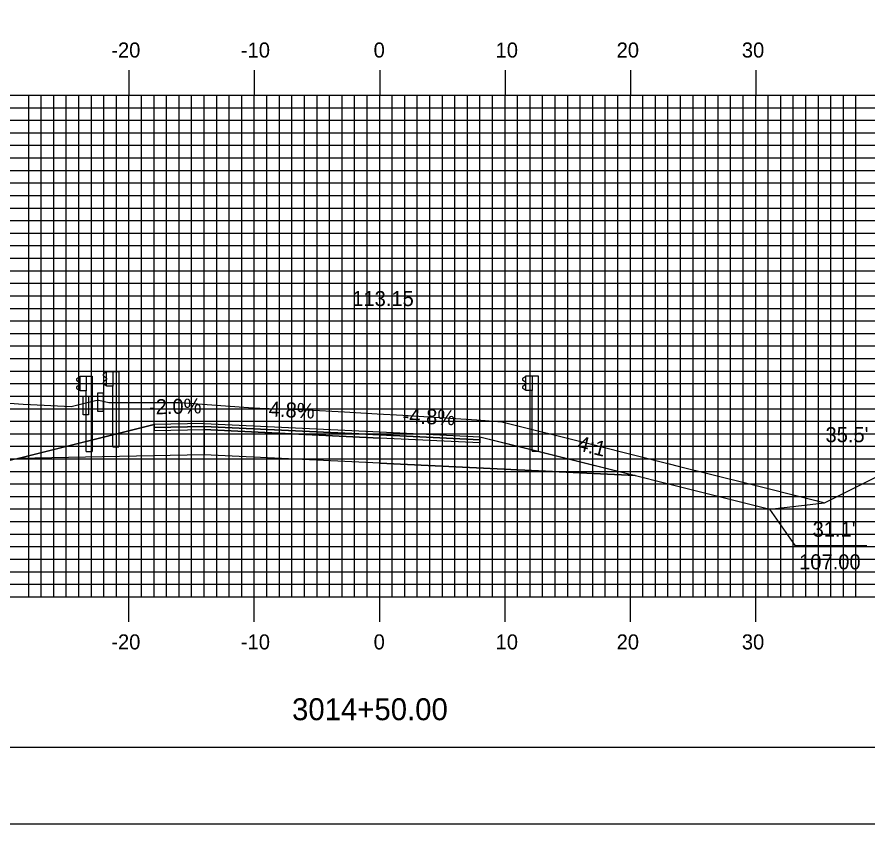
# Model space of a CAD drawing. Extents: x 1684799 to 1685142, y 461260 to 461480.
# Drawn here: x 1684935.8 to 1685003.7, y 461260 to 461324.3 of the extents above; entities that cross this region are included whole.
import ezdxf

# ---------------------------------------------------------------- set-up
doc = ezdxf.new("R2010")
doc.units = 0
for name, color, linetype in [('ANNOTATION', 7, 'Continuous'), ('BORDER', 7, 'Continuous'), ('D_Roadway_Centerline_Text', 7, 'Continuous'), ('D_Roadway_Edge_Shoulder', 7, 'Continuous'), ('D_Roadway_Edge_TW', 7, 'Continuous'), ('D_Roadway_Pavement', 7, 'Continuous'), ('D_Roadway_SlopeLines', 7, 'Continuous'), ('D_Roadway_SubGrade', 7, 'Continuous'), ('D_Text_Standard', 7, 'Continuous'), ('H_V ANNOTATION', 7, 'Continuous'), ('M_Guardrail', 7, 'Continuous'), ('M_Roadway_Centerline', 7, 'Continuous'), ('MAJOR', 7, 'Continuous'), ('MINOR', 7, 'Continuous'), ('PLOT BOUNDARY', 7, 'Continuous'), ('S_Curb_Type_1', 7, 'Continuous'), ('S_Guardrail_Beam', 7, 'Continuous'), ('S_Roadway_Centerline', 7, 'Continuous')]:
    doc.layers.add(name, color=color, linetype=linetype)

msp = doc.modelspace()

# ---------------------------------------------------------------- linework, layer by layer
at = {"layer": 'ANNOTATION'}
msp.add_lwpolyline([(1685003.594, 461282.132), (1684997.903, 461282.132), (1684995.851, 461285.053)], dxfattribs=at)
at = {"layer": 'BORDER'}
msp.add_lwpolyline([(1684815.116, 461266.072), (1685135.116, 461266.072), (1685135.116, 461476.072), (1684815.116, 461476.072)], close=True, dxfattribs=at)
at = {"layer": 'D_Roadway_Edge_Shoulder'}
for points in [[(1684950.716, 461291.9), (1684946.716, 461291.82), (1684946.716, 461291.57), (1684950.716, 461291.65)], [(1684950.716, 461291.65), (1684946.716, 461291.57), (1684946.716, 461291.32), (1684950.716, 461291.4)], [(1684964.716, 461291.223), (1684972.716, 461290.837), (1684972.716, 461290.587), (1684964.716, 461290.973)], [(1684964.716, 461290.973), (1684972.716, 461290.587), (1684972.716, 461290.337), (1684964.716, 461290.723)]]:
    msp.add_lwpolyline(points, close=True, dxfattribs=at)
at = {"layer": 'D_Roadway_Edge_TW'}
msp.add_lwpolyline([(1684950.716, 461291.9), (1684964.716, 461291.223), (1684964.716, 461290.973), (1684950.716, 461291.65)], close=True, dxfattribs=at)
at = {"layer": 'D_Roadway_Pavement'}
msp.add_lwpolyline([(1684950.716, 461291.65), (1684964.716, 461290.973), (1684964.716, 461290.723), (1684950.716, 461291.4)], close=True, dxfattribs=at)
for points in [[(1684950.716, 461291.65), (1684950.716, 461291.4)], [(1684950.716, 461291.65), (1684950.716, 461291.4)], [(1684964.716, 461290.973), (1684964.716, 461290.723)], [(1684964.716, 461290.973), (1684964.716, 461290.723)], [(1684964.716, 461290.973), (1684964.716, 461290.723)]]:
    msp.add_lwpolyline(points, dxfattribs=at)
at = {"layer": 'D_Roadway_SlopeLines'}
msp.add_line((1684964.716, 461288.723), (1684985.112, 461287.738), dxfattribs=at)
for points in [[(1684946.716, 461291.82), (1684918.647, 461284.802)], [(1684972.716, 461290.837), (1684976.716, 461289.837), (1684995.851, 461285.053), (1685000.197, 461285.571)]]:
    msp.add_lwpolyline(points, dxfattribs=at)
at = {"layer": 'D_Roadway_SubGrade'}
for points in [[(1684950.716, 461289.4), (1684935.847, 461289.102), (1684946.716, 461291.82), (1684946.716, 461291.57), (1684950.716, 461291.65), (1684950.716, 461291.4)], [(1684950.716, 461291.4), (1684964.716, 461290.723), (1684964.716, 461288.723), (1684950.716, 461289.4)], [(1684964.716, 461290.723), (1684964.716, 461290.973), (1684972.716, 461290.587), (1684972.716, 461290.837), (1684985.112, 461287.738), (1684964.716, 461288.723)]]:
    msp.add_lwpolyline(points, close=True, dxfattribs=at)
at = {"layer": 'M_Guardrail'}
for p, q in [((1684976.291, 461295.588), (1684976.148, 461295.488)), ((1684976.39, 461295.609), (1684976.308, 461295.595)), ((1684976.39, 461295.682), (1684976.88, 461295.682)), ((1684976.39, 461294.515), (1684976.39, 461295.682)), ((1684976.88, 461295.682), (1684977.371, 461295.682)), ((1684976.88, 461295.682), (1684976.88, 461294.515)), ((1684977.371, 461295.682), (1684977.371, 461289.682)), ((1684976.148, 461295.345), (1684976.343, 461295.209)), ((1684976.343, 461294.989), (1684976.148, 461294.853)), ((1684976.377, 461295.144), (1684976.377, 461295.053)), ((1684976.148, 461294.71), (1684976.291, 461294.61)), ((1684976.308, 461294.603), (1684976.39, 461294.588)), ((1684976.88, 461294.515), (1684976.39, 461294.515)), ((1684976.88, 461289.682), (1684976.88, 461294.515)), ((1684976.88, 461289.682), (1684977.371, 461289.682))]:
    msp.add_line(p, q, dxfattribs=at)
for centre, major_axis, start_param, end_param in [((1684976.198, 461295.416), (-0.0877, 0), 5.323254, 7.243116), ((1684976.315, 461295.554), (-0.0417, 0), 4.886922, 5.323254), ((1684976.198, 461294.781), (-0.0877, 0), 5.323254, 7.243116), ((1684976.298, 461295.144), (0.0789, 0), 0, 0.959931), ((1684976.298, 461295.053), (0.0789, 0), 5.323254, 6.283185), ((1684976.315, 461294.644), (-0.0417, 0), 0.959931, 1.396263)]:
    msp.add_ellipse(centre, major_axis=major_axis, ratio=0.995501, start_param=start_param, end_param=end_param, dxfattribs=at)
at = {"layer": 'MAJOR'}
for p, q in [((1684944.716, 461320.076), (1684944.716, 461318.072)), ((1684954.716, 461320.076), (1684954.716, 461318.072)), ((1684964.716, 461320.076), (1684964.716, 461318.072)), ((1684974.716, 461320.076), (1684974.716, 461318.072)), ((1684984.716, 461320.076), (1684984.716, 461318.072)), ((1684994.716, 461320.076), (1684994.716, 461318.072)), ((1684824.716, 461318.072), (1685104.716, 461318.072)), ((1684824.716, 461318.072), (1685104.716, 461318.072)), ((1684944.716, 461278.072), (1684944.716, 461318.072)), ((1684954.716, 461278.072), (1684954.716, 461318.072)), ((1684964.716, 461278.072), (1684964.716, 461318.072)), ((1684974.716, 461278.072), (1684974.716, 461318.072)), ((1684984.716, 461278.072), (1684984.716, 461318.072)), ((1684994.716, 461278.072), (1684994.716, 461318.072)), ((1684824.716, 461313.072), (1685104.716, 461313.072)), ((1684824.716, 461308.072), (1685104.716, 461308.072)), ((1684824.716, 461303.072), (1685104.716, 461303.072)), ((1684824.716, 461298.072), (1685104.716, 461298.072)), ((1684824.716, 461293.072), (1685104.716, 461293.072)), ((1684824.716, 461288.072), (1685104.716, 461288.072)), ((1684824.716, 461283.072), (1685104.716, 461283.072)), ((1684824.716, 461278.072), (1685104.716, 461278.072)), ((1684824.716, 461278.072), (1685104.716, 461278.072)), ((1684944.716, 461276.068), (1684944.716, 461278.072)), ((1684954.716, 461276.068), (1684954.716, 461278.072)), ((1684964.716, 461276.068), (1684964.716, 461278.072)), ((1684974.716, 461276.068), (1684974.716, 461278.072)), ((1684984.716, 461276.068), (1684984.716, 461278.072)), ((1684994.716, 461276.068), (1684994.716, 461278.072))]:
    msp.add_line(p, q, dxfattribs=at)
at = {"layer": 'MINOR'}
for p, q in [((1684936.716, 461278.072), (1684936.716, 461318.072)), ((1684937.716, 461278.072), (1684937.716, 461318.072)), ((1684938.716, 461278.072), (1684938.716, 461318.072)), ((1684939.716, 461278.072), (1684939.716, 461318.072)), ((1684940.716, 461278.072), (1684940.716, 461318.072)), ((1684941.716, 461278.072), (1684941.716, 461318.072)), ((1684942.716, 461278.072), (1684942.716, 461318.072)), ((1684943.716, 461278.072), (1684943.716, 461318.072)), ((1684945.716, 461278.072), (1684945.716, 461318.072)), ((1684946.716, 461278.072), (1684946.716, 461318.072)), ((1684947.716, 461278.072), (1684947.716, 461318.072)), ((1684948.716, 461278.072), (1684948.716, 461318.072)), ((1684949.716, 461278.072), (1684949.716, 461318.072)), ((1684950.716, 461278.072), (1684950.716, 461318.072)), ((1684951.716, 461278.072), (1684951.716, 461318.072)), ((1684952.716, 461278.072), (1684952.716, 461318.072)), ((1684953.716, 461278.072), (1684953.716, 461318.072)), ((1684955.716, 461278.072), (1684955.716, 461318.072)), ((1684956.716, 461278.072), (1684956.716, 461318.072)), ((1684957.716, 461278.072), (1684957.716, 461318.072)), ((1684958.716, 461278.072), (1684958.716, 461318.072)), ((1684959.716, 461278.072), (1684959.716, 461318.072)), ((1684960.716, 461278.072), (1684960.716, 461318.072)), ((1684961.716, 461278.072), (1684961.716, 461318.072)), ((1684962.716, 461278.072), (1684962.716, 461318.072)), ((1684963.716, 461278.072), (1684963.716, 461318.072)), ((1684965.716, 461278.072), (1684965.716, 461318.072)), ((1684966.716, 461278.072), (1684966.716, 461318.072)), ((1684967.716, 461278.072), (1684967.716, 461318.072)), ((1684968.716, 461278.072), (1684968.716, 461318.072)), ((1684969.716, 461278.072), (1684969.716, 461318.072)), ((1684970.716, 461278.072), (1684970.716, 461318.072)), ((1684971.716, 461278.072), (1684971.716, 461318.072)), ((1684972.716, 461278.072), (1684972.716, 461318.072)), ((1684973.716, 461278.072), (1684973.716, 461318.072)), ((1684975.716, 461278.072), (1684975.716, 461318.072)), ((1684976.716, 461278.072), (1684976.716, 461318.072)), ((1684977.716, 461278.072), (1684977.716, 461318.072)), ((1684978.716, 461278.072), (1684978.716, 461318.072)), ((1684979.716, 461278.072), (1684979.716, 461318.072)), ((1684980.716, 461278.072), (1684980.716, 461318.072)), ((1684981.716, 461278.072), (1684981.716, 461318.072)), ((1684982.716, 461278.072), (1684982.716, 461318.072)), ((1684983.716, 461278.072), (1684983.716, 461318.072)), ((1684985.716, 461278.072), (1684985.716, 461318.072)), ((1684986.716, 461278.072), (1684986.716, 461318.072)), ((1684987.716, 461278.072), (1684987.716, 461318.072)), ((1684988.716, 461278.072), (1684988.716, 461318.072)), ((1684989.716, 461278.072), (1684989.716, 461318.072)), ((1684990.716, 461278.072), (1684990.716, 461318.072)), ((1684991.716, 461278.072), (1684991.716, 461318.072)), ((1684992.716, 461278.072), (1684992.716, 461318.072)), ((1684993.716, 461278.072), (1684993.716, 461318.072)), ((1684995.716, 461278.072), (1684995.716, 461318.072)), ((1684996.716, 461278.072), (1684996.716, 461318.072)), ((1684997.716, 461278.072), (1684997.716, 461318.072)), ((1684998.716, 461278.072), (1684998.716, 461318.072)), ((1684999.716, 461278.072), (1684999.716, 461318.072)), ((1685000.716, 461278.072), (1685000.716, 461318.072)), ((1685001.716, 461278.072), (1685001.716, 461318.072)), ((1685002.716, 461278.072), (1685002.716, 461318.072)), ((1684824.716, 461317.072), (1685104.716, 461317.072)), ((1684824.716, 461316.072), (1685104.716, 461316.072)), ((1684824.716, 461315.072), (1685104.716, 461315.072)), ((1684824.716, 461314.072), (1685104.716, 461314.072)), ((1684824.716, 461312.072), (1685104.716, 461312.072)), ((1684824.716, 461311.072), (1685104.716, 461311.072)), ((1684824.716, 461310.072), (1685104.716, 461310.072)), ((1684824.716, 461309.072), (1685104.716, 461309.072)), ((1684824.716, 461307.072), (1685104.716, 461307.072)), ((1684824.716, 461306.072), (1685104.716, 461306.072)), ((1684824.716, 461305.072), (1685104.716, 461305.072)), ((1684824.716, 461304.072), (1685104.716, 461304.072)), ((1684824.716, 461302.072), (1685104.716, 461302.072)), ((1684824.716, 461301.072), (1685104.716, 461301.072)), ((1684824.716, 461300.072), (1685104.716, 461300.072)), ((1684824.716, 461299.072), (1685104.716, 461299.072)), ((1684824.716, 461297.072), (1685104.716, 461297.072)), ((1684824.716, 461296.072), (1685104.716, 461296.072)), ((1684824.716, 461295.072), (1685104.716, 461295.072)), ((1684824.716, 461294.072), (1685104.716, 461294.072)), ((1684824.716, 461292.072), (1685104.716, 461292.072)), ((1684824.716, 461291.072), (1685104.716, 461291.072)), ((1684824.716, 461290.072), (1685104.716, 461290.072)), ((1684824.716, 461289.072), (1685104.716, 461289.072)), ((1684824.716, 461287.072), (1685104.716, 461287.072)), ((1684824.716, 461286.072), (1685104.716, 461286.072)), ((1684824.716, 461285.072), (1685104.716, 461285.072)), ((1684824.716, 461284.072), (1685104.716, 461284.072)), ((1684824.716, 461282.072), (1685104.716, 461282.072)), ((1684824.716, 461281.072), (1685104.716, 461281.072)), ((1684824.716, 461280.072), (1685104.716, 461280.072)), ((1684824.716, 461279.072), (1685104.716, 461279.072))]:
    msp.add_line(p, q, dxfattribs=at)
at = {"layer": 'PLOT BOUNDARY'}
msp.add_lwpolyline([(1684798.93, 461259.954), (1685138.93, 461259.954), (1685138.93, 461479.954), (1684798.93, 461479.954)], close=True, dxfattribs=at)
at = {"layer": 'S_Curb_Type_1'}
for points in [[(1684941.062, 461294.072), (1684941.479, 461294.072), (1684941.479, 461292.572), (1684941.062, 461292.572)], [(1684941.062, 461294.072), (1684941.479, 461294.072), (1684941.479, 461292.572), (1684941.062, 461292.572)], [(1684942.228, 461294.345), (1684942.645, 461294.345), (1684942.645, 461292.845), (1684942.228, 461292.845)], [(1684942.228, 461294.345), (1684942.645, 461294.345), (1684942.645, 461292.845), (1684942.228, 461292.845)]]:
    msp.add_lwpolyline(points, close=True, dxfattribs=at)
at = {"layer": 'S_Guardrail_Beam'}
for p, q in [((1684940.71, 461295.561), (1684940.567, 461295.461)), ((1684940.71, 461295.561), (1684940.567, 461295.461)), ((1684940.809, 461295.583), (1684940.727, 461295.568)), ((1684940.809, 461295.583), (1684940.727, 461295.568)), ((1684940.809, 461295.656), (1684941.299, 461295.656)), ((1684940.809, 461294.489), (1684940.809, 461295.656)), ((1684940.809, 461295.656), (1684941.299, 461295.656)), ((1684940.809, 461294.489), (1684940.809, 461295.656)), ((1684941.299, 461295.656), (1684941.79, 461295.656)), ((1684941.299, 461295.656), (1684941.299, 461294.489)), ((1684941.299, 461295.656), (1684941.79, 461295.656)), ((1684941.299, 461295.656), (1684941.299, 461294.489)), ((1684941.79, 461295.656), (1684941.79, 461289.656)), ((1684941.79, 461295.656), (1684941.79, 461289.656)), ((1684942.826, 461295.939), (1684942.683, 461295.839)), ((1684942.826, 461295.939), (1684942.683, 461295.839)), ((1684942.683, 461295.696), (1684942.878, 461295.559)), ((1684942.683, 461295.696), (1684942.878, 461295.559)), ((1684942.925, 461295.96), (1684942.843, 461295.945)), ((1684942.925, 461295.96), (1684942.843, 461295.945)), ((1684942.912, 461295.495), (1684942.912, 461295.404)), ((1684942.912, 461295.495), (1684942.912, 461295.404)), ((1684942.925, 461296.033), (1684943.415, 461296.033)), ((1684942.925, 461294.866), (1684942.925, 461296.033)), ((1684942.925, 461296.033), (1684943.415, 461296.033)), ((1684942.925, 461294.866), (1684942.925, 461296.033)), ((1684943.415, 461296.033), (1684943.906, 461296.033)), ((1684943.415, 461296.033), (1684943.415, 461294.866)), ((1684943.415, 461296.033), (1684943.906, 461296.033)), ((1684943.415, 461296.033), (1684943.415, 461294.866)), ((1684943.906, 461296.033), (1684943.906, 461290.033)), ((1684943.906, 461296.033), (1684943.906, 461290.033)), ((1684940.567, 461295.318), (1684940.762, 461295.182)), ((1684940.567, 461295.318), (1684940.762, 461295.182)), ((1684940.762, 461294.962), (1684940.567, 461294.826)), ((1684940.762, 461294.962), (1684940.567, 461294.826)), ((1684940.796, 461295.118), (1684940.796, 461295.027)), ((1684940.796, 461295.118), (1684940.796, 461295.027)), ((1684942.878, 461295.34), (1684942.683, 461295.203)), ((1684942.878, 461295.34), (1684942.683, 461295.203)), ((1684942.683, 461295.06), (1684942.826, 461294.96)), ((1684942.683, 461295.06), (1684942.826, 461294.96)), ((1684942.843, 461294.953), (1684942.925, 461294.939)), ((1684942.843, 461294.953), (1684942.925, 461294.939)), ((1684943.415, 461294.866), (1684942.925, 461294.866)), ((1684943.415, 461294.866), (1684942.925, 461294.866)), ((1684943.415, 461290.033), (1684943.415, 461294.866)), ((1684943.415, 461290.033), (1684943.415, 461294.866)), ((1684940.567, 461294.683), (1684940.71, 461294.583)), ((1684940.567, 461294.683), (1684940.71, 461294.583)), ((1684940.727, 461294.576), (1684940.809, 461294.562)), ((1684940.727, 461294.576), (1684940.809, 461294.562)), ((1684941.299, 461294.489), (1684940.809, 461294.489)), ((1684941.299, 461294.489), (1684940.809, 461294.489)), ((1684941.299, 461289.656), (1684941.299, 461294.489)), ((1684941.299, 461289.656), (1684941.299, 461294.489)), ((1684943.415, 461290.033), (1684943.906, 461290.033)), ((1684943.415, 461290.033), (1684943.906, 461290.033)), ((1684941.299, 461289.656), (1684941.79, 461289.656)), ((1684941.299, 461289.656), (1684941.79, 461289.656))]:
    msp.add_line(p, q, dxfattribs=at)
for centre, major_axis, start_param, end_param in [((1684940.617, 461295.39), (-0.0877, 0), 5.323254, 7.243116), ((1684940.617, 461295.39), (-0.0877, 0), 5.323254, 7.243116), ((1684940.734, 461295.527), (-0.0417, 0), 4.886922, 5.323254), ((1684940.734, 461295.527), (-0.0417, 0), 4.886922, 5.323254), ((1684942.733, 461295.767), (-0.0877, 0), 5.323254, 7.243116), ((1684942.733, 461295.767), (-0.0877, 0), 5.323254, 7.243116), ((1684942.85, 461295.905), (-0.0417, 0), 4.886922, 5.323254), ((1684942.85, 461295.905), (-0.0417, 0), 4.886922, 5.323254), ((1684942.833, 461295.495), (0.0789, 0), 0, 0.959931), ((1684942.833, 461295.495), (0.0789, 0), 0, 0.959931), ((1684942.833, 461295.404), (0.0789, 0), 5.323254, 6.283185), ((1684942.833, 461295.404), (0.0789, 0), 5.323254, 6.283185), ((1684940.617, 461294.755), (-0.0877, 0), 5.323254, 7.243116), ((1684940.617, 461294.755), (-0.0877, 0), 5.323254, 7.243116), ((1684940.717, 461295.118), (0.0789, 0), 0, 0.959931), ((1684940.717, 461295.118), (0.0789, 0), 0, 0.959931), ((1684940.717, 461295.027), (0.0789, 0), 5.323254, 6.283185), ((1684940.717, 461295.027), (0.0789, 0), 5.323254, 6.283185), ((1684942.733, 461295.132), (-0.0877, 0), 5.323254, 7.243116), ((1684942.733, 461295.132), (-0.0877, 0), 5.323254, 7.243116), ((1684942.85, 461294.994), (-0.0417, 0), 0.959931, 1.396263), ((1684942.85, 461294.994), (-0.0417, 0), 0.959931, 1.396263), ((1684940.734, 461294.617), (-0.0417, 0), 0.959931, 1.396263), ((1684940.734, 461294.617), (-0.0417, 0), 0.959931, 1.396263)]:
    msp.add_ellipse(centre, major_axis=major_axis, ratio=0.995501, start_param=start_param, end_param=end_param, dxfattribs=at)
at = {"layer": 'S_Roadway_Centerline'}
for points in [[(1684935.179, 461293.501), (1684936.278, 461293.428), (1684936.861, 461293.396), (1684940.114, 461293.243), (1684940.633, 461293.391), (1684941.062, 461293.489), (1684942.051, 461293.715), (1684942.228, 461293.762), (1684942.309, 461293.738), (1684943.101, 461293.561), (1684944.246, 461293.562), (1684946.283, 461293.562), (1684948.736, 461293.567), (1684954.241, 461293.163), (1684955.165, 461293.102), (1684958.903, 461292.991), (1684961.916, 461292.821), (1684964.522, 461292.669), (1684966.571, 461292.556), (1684972.474, 461292.176), (1684974.453, 461292.028)], [(1684974.453, 461292.028), (1684981.617, 461290.231), (1684982.004, 461290.133), (1684987.808, 461288.678), (1684988.544, 461288.493), (1684993.998, 461287.125), (1684999.516, 461285.741), (1685000.023, 461285.615), (1685000.197, 461285.571), (1685004.25, 461287.58)]]:
    msp.add_lwpolyline(points, dxfattribs=at)

# ---------------------------------------------------------------- texts
at = {"layer": 'ANNOTATION'}
for s, rotation, p in [('-2.0%', 1.14576, (1684946.322, 461292.612)), ('4.8%', 357.23417, (1684955.846, 461292.454)), ('-4.8%', 357.23417, (1684966.525, 461291.938)), ('4:1', 345.96376, (1684980.42, 461289.772))]:
    msp.add_text(s, height=1.2, rotation=rotation, dxfattribs=at).set_placement(p)
for s, p in [("31.1' ", (1684999.259, 461282.858)), ('107.00', (1684998.182, 461280.258))]:
    msp.add_text(s, height=1.2, dxfattribs=at).set_placement(p)
at = {"layer": 'D_Roadway_Centerline_Text'}
msp.add_text('113.15', height=1.2, dxfattribs=at).set_placement((1684962.528, 461301.253))
at = {"layer": 'D_Text_Standard'}
msp.add_text("35.5'", height=1.2, dxfattribs=at).set_placement((1685000.289, 461290.398))
at = {"layer": 'H_V ANNOTATION'}
for s, height, p in [('-20', 1.2, (1684943.303, 461321.072)), ('-10', 1.2, (1684953.646, 461321.072)), ('0', 1.2, (1684964.234, 461321.072)), ('10', 1.2, (1684973.967, 461321.072)), ('20', 1.2, (1684983.624, 461321.072)), ('30', 1.2, (1684993.614, 461321.072)), ('-20', 1.2, (1684943.303, 461273.872)), ('-10', 1.2, (1684953.646, 461273.872)), ('0', 1.2, (1684964.234, 461273.872)), ('10', 1.2, (1684973.967, 461273.872)), ('20', 1.2, (1684983.624, 461273.872)), ('30', 1.2, (1684993.614, 461273.872)), ('3014+50.00', 1.75, (1684957.725, 461268.228))]:
    msp.add_text(s, height=height, dxfattribs=at).set_placement(p)
at = {"layer": 'M_Roadway_Centerline'}
for s, p in [('C', (1684958.898, 461292.991)), ('L', (1684958.903, 461292.984))]:
    msp.add_text(s, height=0.0146, dxfattribs=at).set_placement(p)

doc.saveas('drawing.dxf')
